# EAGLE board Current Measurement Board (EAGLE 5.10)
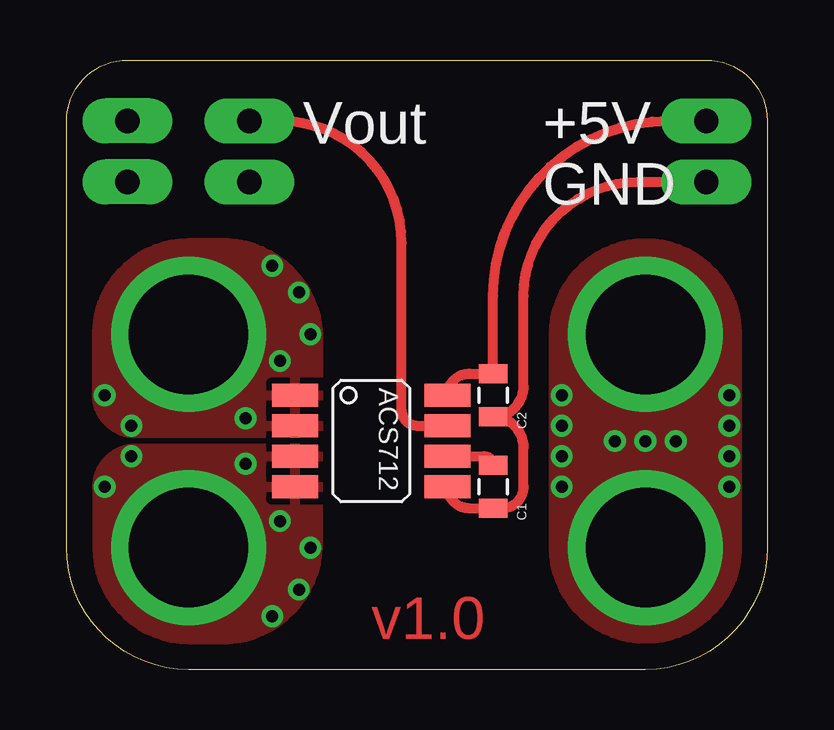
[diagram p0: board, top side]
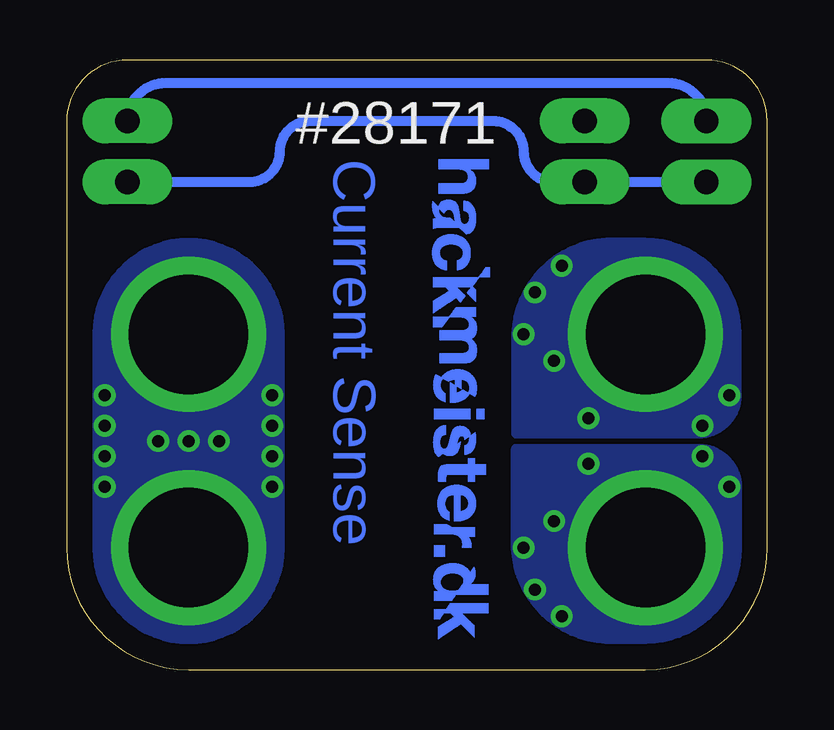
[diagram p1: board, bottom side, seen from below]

Size 29.21 x 25.4 mm. Coordinates in mm from the lower left corner, seen from the top.
Outline: 0,22.86 arc-90 2.54,25.4 26.67,25.4 arc-90 29.21,22.86 29.21,5.08 arc-90 24.13,0 5.08,0 arc-90 0,5.08 0,22.86
Copper layers (1*16): Top 0.035mm / dielectric 1.5mm / Bottom 0.035mm
Design rules "default *": minimum track width 10mil, minimum drill 0.3mm, track to track 6mil, track to pad 8mil, pad to pad 8mil, via to via 8mil, smd to smd 8mil, copper to edge 40mil, drill to drill 8mil, minimum pad ring 10mil, minimum via ring 8mil, stop-mask expansion 4mil, vias tented up to drill 0mil, thermal gap 10mil

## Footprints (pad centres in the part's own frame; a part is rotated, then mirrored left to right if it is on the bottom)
0805 = smd 0.8 x 1.2: 1 -0.9,0; 2 0.9,0
1X02_LONGPADS = drill 1.016 pad 1.88 long: 1 0,0; 2 2.54,0
SOIC8 = smd 1.93 x 0.965: 1 -4.445,1.27; 2 -4.445,0; 3 -4.445,-1.27; 4 -4.445,-2.54; 5 1.905,-2.54; 6 1.905,-1.27; 7 1.905,0; 8 1.905,1.27

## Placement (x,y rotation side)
C1  1nF  [0805]  17.78,7.62 90 top
C2  0.1uF  [0805]  17.78,11.43 90 top
JP1  POWER  [1X02_LONGPADS]  26.67,22.86 270 top
JP2  POWER  [1X02_LONGPADS]  2.54,20.32 90 top
JP3  OUTPUT  [1X02_LONGPADS]  7.62,22.86 270 top
U$1  ACS712  [SOIC8]  13.97,10.16 0 top
U$4  [HACKMEISTER-LOGO-20MM-BOTTOM]  13.97,1.27 90 top

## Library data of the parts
C1 C2 JP1-JP3 = SparkFun
U$1 = Pauls_parts
U$4 = hackmeisterdk

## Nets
5V: C2.2 JP1.1 JP2.2 U$1.8
GND: C1.1 C2.1 JP1.2 JP2.1 JP3.2 U$1.5
N$1: C1.2 U$1.6
N$6: JP3.1 U$1.7
SENSE_MINUS: U$1.3 U$1.4
SENSE_PLUS: U$1.1 U$1.2

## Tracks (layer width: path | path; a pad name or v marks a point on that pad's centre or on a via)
5V
  Top 0.406: JP1.1 25.08,22.86 arc90 17.78,15.56 C2.2 16.77,12.33 arc90 U$1.8
  Bottom 0.406: JP2.2 arc-90 4.13,24.45 25.08,24.45 arc-90 JP1.1
GND
  Top 0.406: JP1.2 23.81,20.32 arc90 19.05,15.56 19.05,11.8 arc-90 C2.1 arc-90 19.05,9.26 19.05,7.62 arc-90 18.15,6.72 C1.1 16.77,6.72 arc-90 U$1.5
  Bottom 0.406: JP2.1 JP3.2 8.89,20.32 arc90 10.16,21.59 arc-90 11.43,22.86 19.05,22.86 arc-90 20.32,21.59 arc90 21.59,20.32 JP1.2
N$1
  Top 0.406: U$1.6 17.41,8.89 arc-90 C1.2
N$6
  Top 0.406: 14.61,10.16 arc-90 13.97,10.79 13.97,17.78 arc90 8.89,22.86 JP3.1 | 14.61,10.16 arc90 14.61,10.16 | 14.61,10.16 U$1.7
SENSE_GND  (via drill 0.5, 4.98 pad 6.45)
  other vias: 24.13,13.97 24.13,5.08 20.64,11.43 20.64,10.16 20.64,8.89 20.64,7.62 22.86,9.53 24.13,9.53 25.4,9.53 27.62,7.62 27.62,8.89 27.62,10.16 27.62,11.43
  pour Bottom: 20.32,13.97 arc-90 24.13,17.78 arc-90 27.94,13.97 27.94,5.08 arc-90 24.13,1.27 arc-90 20.32,5.08
  pour Top: 20.32,13.97 arc-90 24.13,17.78 arc-90 27.94,13.97 27.94,5.08 arc-90 24.13,1.27 arc-90 20.32,5.08
SENSE_MINUS  (via drill 0.5, 4.98 pad 6.45)
  other vias: 5.08,5.08 10.16,5.08 9.68,3.33 8.57,2.22 2.7,8.89 1.59,7.62 7.46,8.57 8.89,6.19
  pour Bottom: 1.27,5.08 arc90 5.08,1.27 6.35,1.27 arc90 10.48,5.08 10.48,9.21 2.86,9.21 arc90 1.27,7.62
  pour Top: 1.27,5.08 arc90 5.08,1.27 6.35,1.27 arc90 10.48,5.08 10.48,9.21 2.86,9.21 arc90 1.27,7.62
SENSE_PLUS  (via drill 0.5, 4.98 pad 6.45)
  other vias: 5.08,13.97 10.16,13.97 9.68,15.72 8.57,16.83 1.59,11.43 2.7,10.16 7.46,10.48 8.89,12.86
  pour Bottom: 1.27,13.97 arc-90 5.08,17.78 6.35,17.78 arc-90 10.48,13.97 10.48,9.84 2.86,9.84 arc-90 1.27,11.43
  pour Top: 1.27,13.97 arc-90 5.08,17.78 6.35,17.78 arc-90 10.48,13.97 10.48,9.84 2.86,9.84 arc-90 1.27,11.43

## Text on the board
Top: v1.0
Bottom: Current Sense
bPlace: #28171
tNames: Vout | +5V | GND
